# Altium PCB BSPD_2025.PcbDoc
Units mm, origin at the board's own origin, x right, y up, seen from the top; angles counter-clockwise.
Board outline 53 x 50 mm, 2 copper layers (Top Layer, Bottom Layer); 77 components, 28 nets, 170 pads, 103 vias.
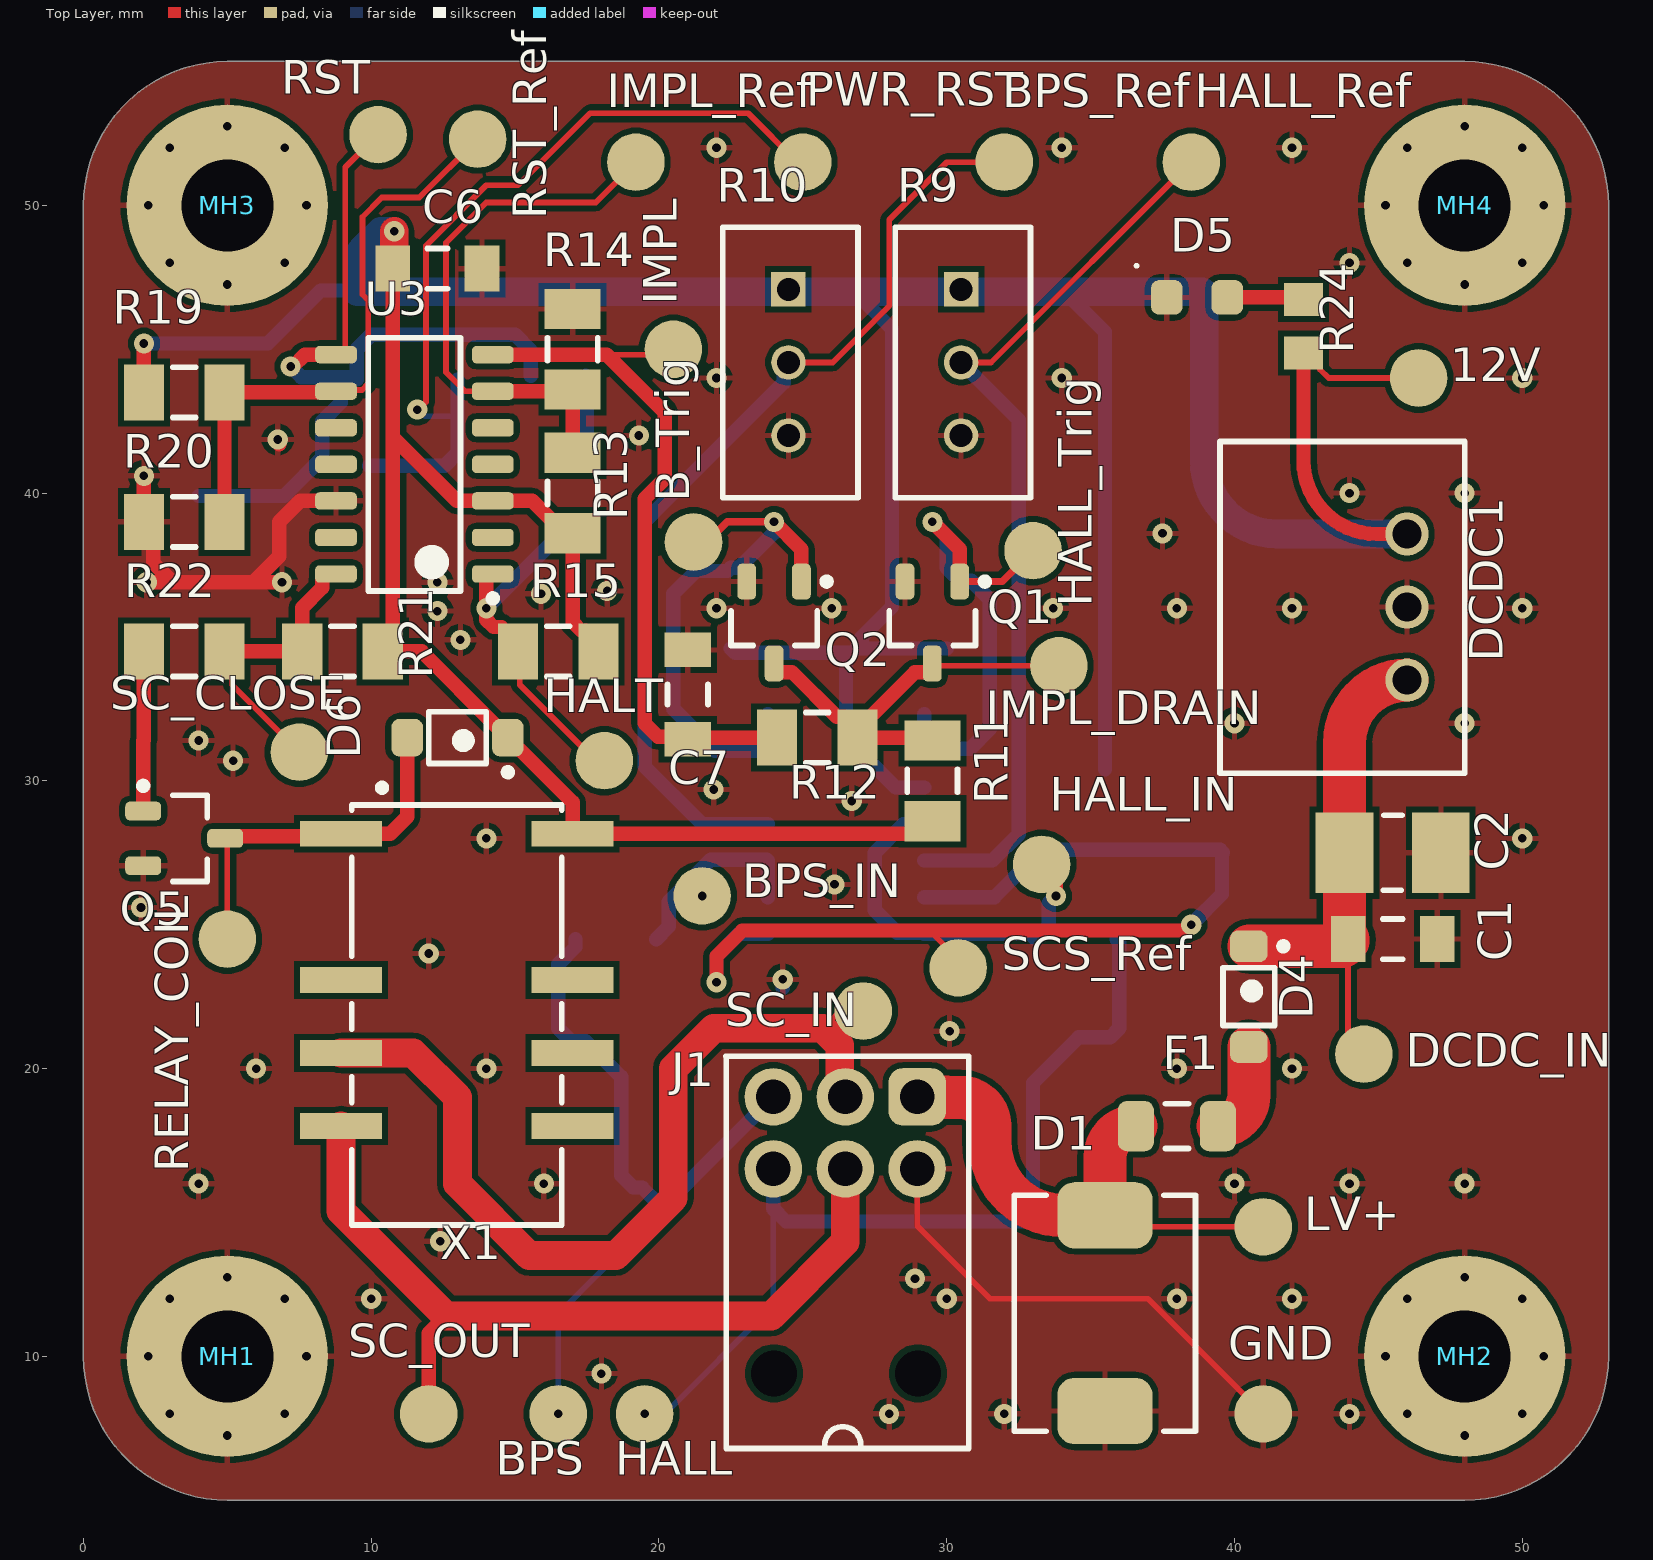
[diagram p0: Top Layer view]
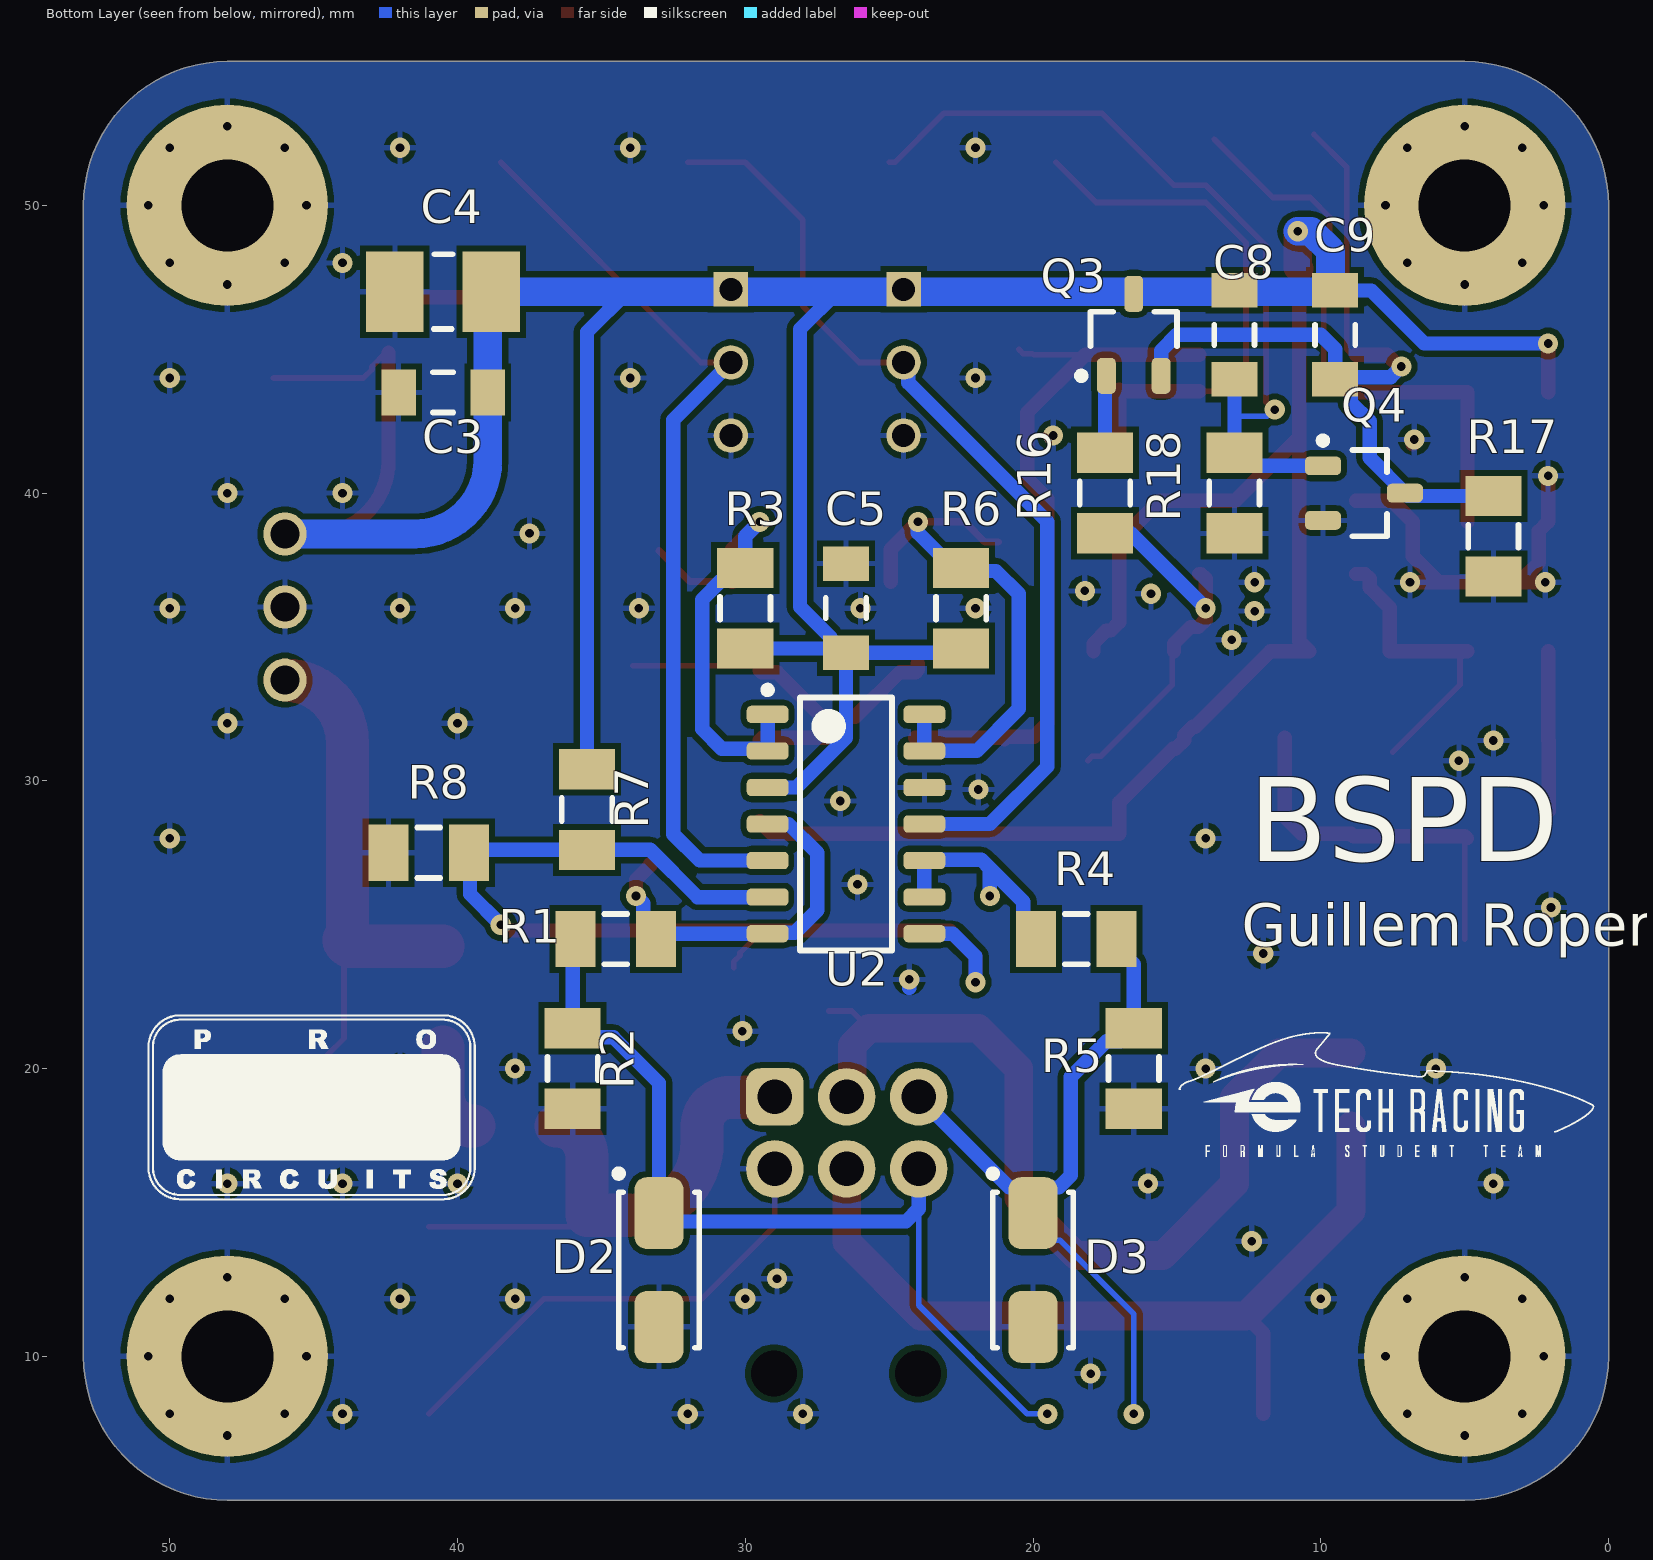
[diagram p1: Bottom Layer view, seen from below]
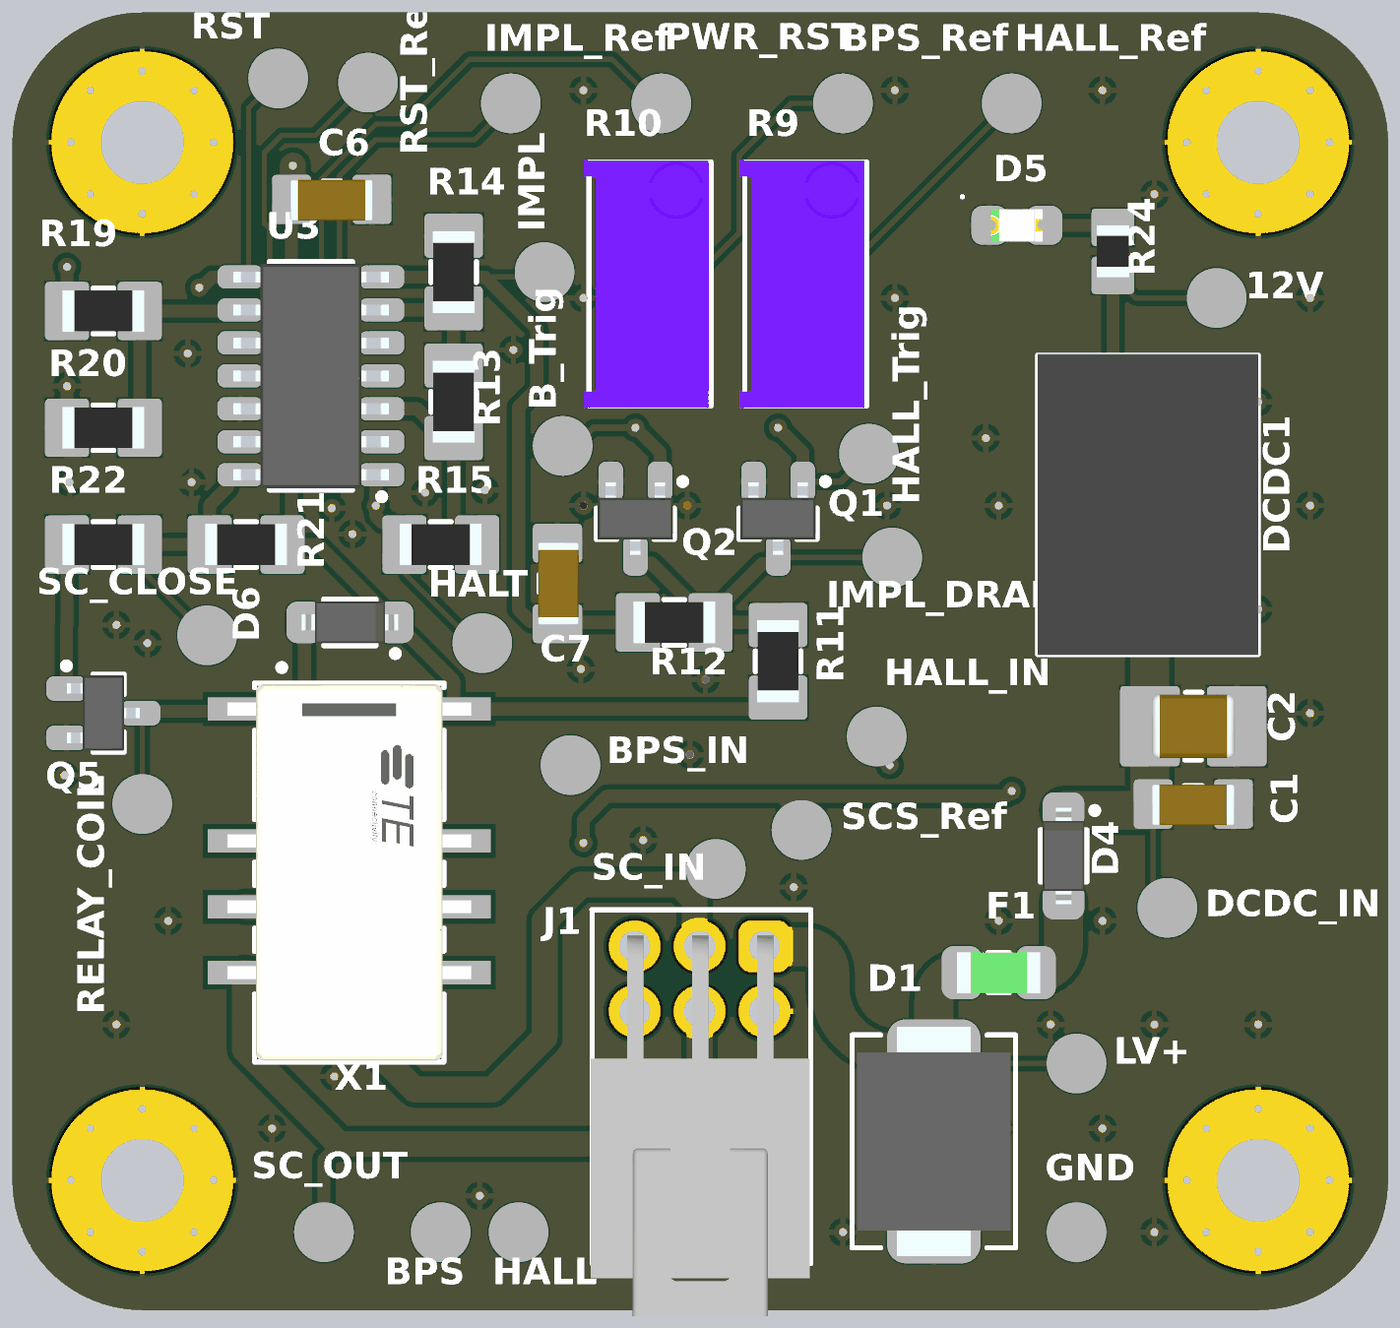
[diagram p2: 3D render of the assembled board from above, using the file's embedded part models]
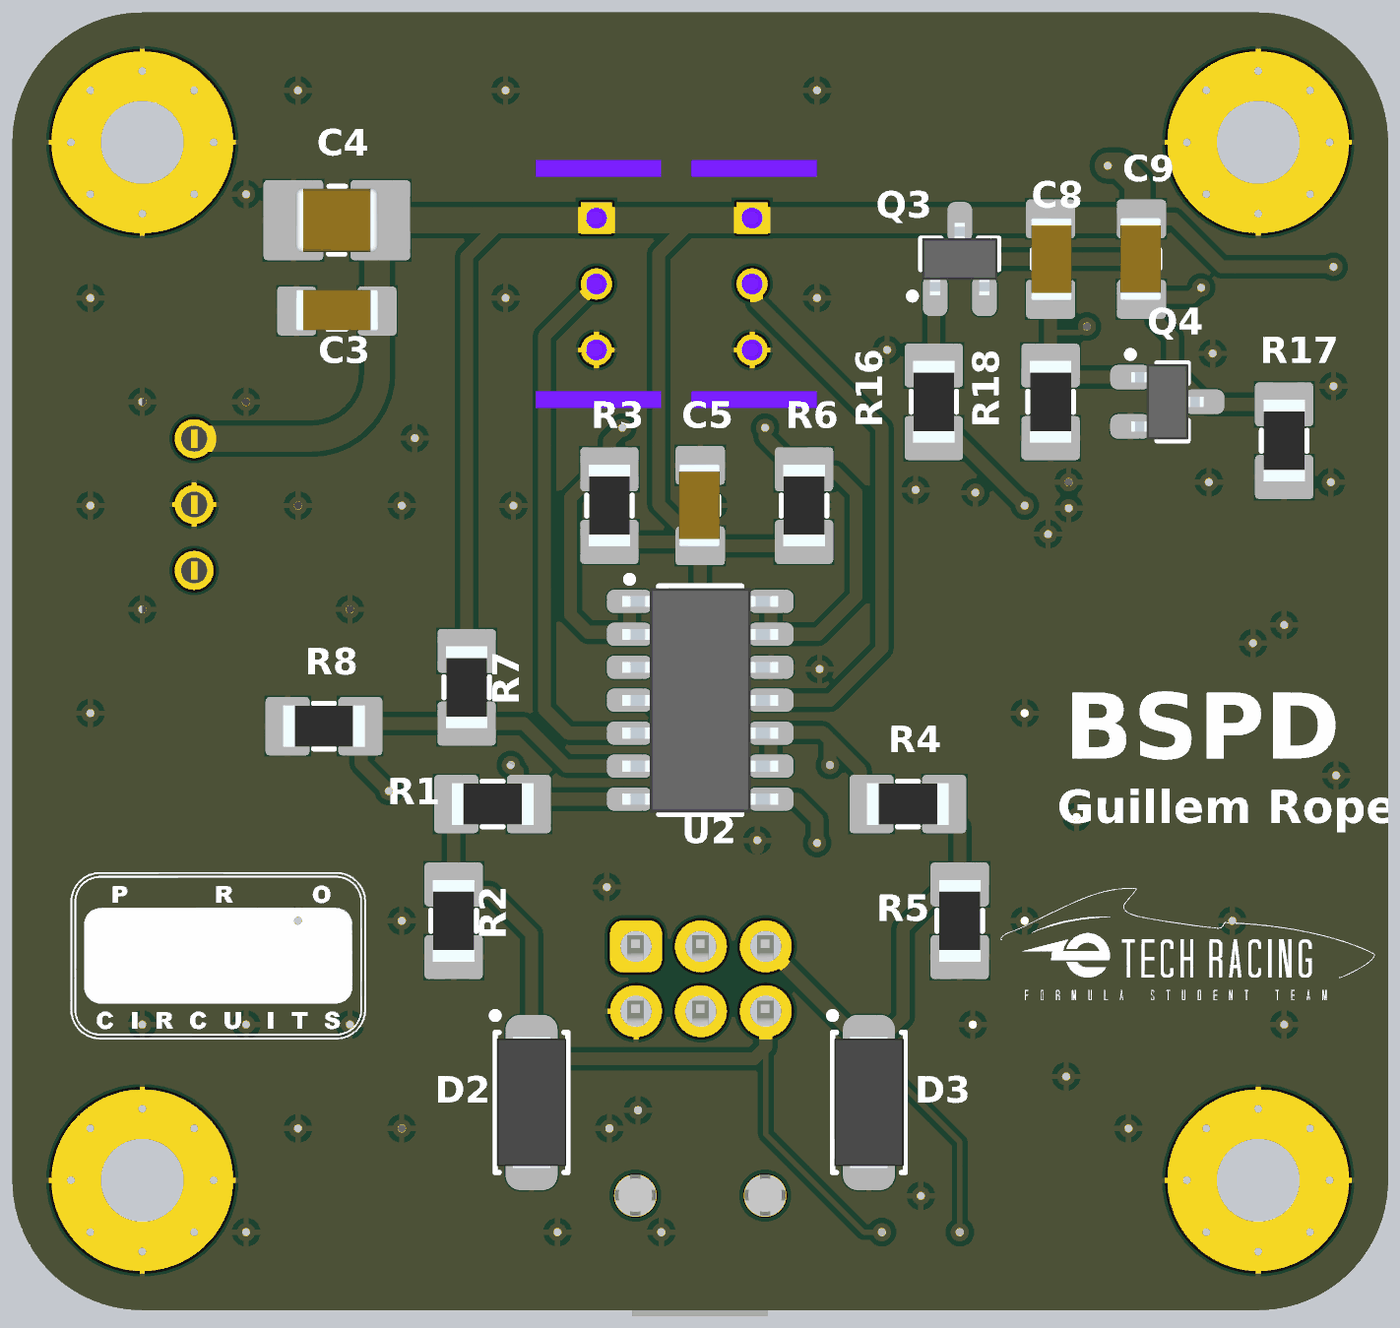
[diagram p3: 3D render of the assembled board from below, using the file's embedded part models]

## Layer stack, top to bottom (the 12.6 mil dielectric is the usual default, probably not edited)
Top Solder: solder mask 0.0102, Solder Resist, Dk 3.5
Top Layer: signal copper 0.0356
Dielectric 1: dielectric 0.32, FR-4, Dk 4.8
Bottom Layer: signal copper 0.0356
Bottom Solder: solder mask 0.0102, Solder Resist, Dk 3.5

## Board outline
0,10 0,50 cw(c5,50) 5,55 48,55 cw(c48,50) 53,50 53,10 cw(c48,10) 48,5 5,5 cw(c5,10)

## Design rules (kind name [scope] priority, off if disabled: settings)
Clearance [All] p1: gap=0.2 ignorepadtopadclearanceinfootprint=FALSE
HoleSize [All] p1: absolutevalues=TRUE maxlimit=5 minlimit=0.2 maxpercent=80.000 minpercent=20.000
HoleToHoleClearance [All] p1: gap=0.3 allowstackedmicrovias=TRUE
MinimumSolderMaskSliver [All] p1: minsoldermaskwidth=0.2
PasteMaskExpansion [All] p1: expansion=0.15
PlaneClearance [All] p1: clearance=0.2
PlaneConnect [All] p1: planeconnectstyle=Relief reliefexpansion=0.3 reliefentries=4 reliefconductorwidth=0.2 reliefairgap=0.2
PolygonConnect [All] p1: connectstyle=Relief reliefconductorwidth=0.2 reliefentries=4 polygonreliefangle="90 Angle" airgapwidth=0.2
RoutingCorners [All] p1: cornerstyle=45-Degree minsetback=2.5 maxsetback=2.5
RoutingVias [All] p1: holewidth=0.3 width=0.5 viastyle="Through Hole" minholewidth=0.3 minwidth=0.5 maxholewidth=2 maxwidth=2.5
SilkToSilkClearance [All] p1: silktosilkclearance=0.2
SilkToSolderMaskClearance [IsPad] p1: minsilkscreentomaskgap=0 clearancetoexposedcopper=TRUE
SolderMaskExpansion [All] p1: expansion=0.1 istentingtop=FALSE
UnRoutedNet [All] p1: checkbadconnections=TRUE
Width [All] p1: maxlimit=5 minlimit=0.2 preferedwidth=0.2
20 further rules are at their usual default settings.

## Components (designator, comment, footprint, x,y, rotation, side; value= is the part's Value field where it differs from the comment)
12V "TestPoint" TestPoint 46.4,44 r90 top
B_Trig "TestPoint" TestPoint 21.2,38.3 r90 top (schematic designator BRAKE_Trig)
BPS "TestPoint" TestPoint 16.5,8 r90 top
BPS_IN "TestPoint" TestPoint 21.5,26 r90 top
BPS_Ref "TestPoint" TestPoint 32,51.5 r90 top
C1 "885012008055" C1206FNPC-RW 45.5,24.5 r180 top
C2 "GRJ32ER71H106KE11L" C10u-50V-1210FNPMLCC-X7R 45.5,27.5 r180 top
C3 "885012008055" C1206FNPC-RW 40.5,43.5 r180 bottom
C4 "GRJ32ER71H106KE11L" C10u-50V-1210FNPMLCC-X7R 40.5,47 r180 bottom
C5 "885012208058" C1206FNPC-RW 26.5,36 r90 bottom
C6 "885012208058" C1206FNPC-RW 12.3,47.8 r180 top
C7 "885012208018" C1206FNPC-RW 21,33 r270 top
C8 "885012208058" C1206FNPC-RW 13,45.5 r270 bottom
C9 "885012208036" C1206FNPC-RW 9.5,45.5 r90 bottom
D1 "824551301" DTVS-DO-214AB 35.5,11.5 r90 top
D2 "824501600" DTVS-DO-214AC 33,13 r90 bottom
D3 "824501600" DTVS-DO-214AC 20,13 r90 bottom
D4 "MBR0530" DSC-SOD123 40.5,22.5 r270 top
D5 "150080VS75000" LED_0805_WE 38.7,46.8 r0 top
D6 "MBR0530" DSC-SOD123 13,31.5 r180 top
DCDC1 "173951236" DCDC_Magi3c 46,36.04 r270 top
DCDC_IN "TestPoint" TestPoint 44.5,20.5 r90 top
F1 "0437001.WRA" Fuse_1206 38,18 r0 top
GND "TestPoint" TestPoint 41,8 r90 top
HALL "TestPoint" TestPoint 19.5,8 r90 top
HALL_IN "TestPoint" TestPoint 33.3,27.1 r90 top
HALL_Ref "TestPoint" TestPoint 38.5,51.5 r90 top
HALL_Trig "TestPoint" TestPoint 33,38 r90 top
HALT "TestPoint" TestPoint 18.1,30.7 r90 top
IMPL "TestPoint" TestPoint 20.5,45 r90 top
IMPL_DRAIN "TestPoint" TestPoint 33.9,34 r90 top
IMPL_Ref "TestPoint" TestPoint 19.2,51.5 r90 top
J1 "J_NanoFit_2x3" J_NanoFit_2x3 26.5,13 r0 top
LV+ "TestPoint" TestPoint 41,14.5 r90 top
MH1 "Mounting_Hole_M3" Mounting_Hole_M3 5,10 r0 top
MH2 "Mounting_Hole_M3" Mounting_Hole_M3 48,10 r0 top
MH3 "Mounting_Hole_M3" Mounting_Hole_M3 5,50 r0 top
MH4 "Mounting_Hole_M3" Mounting_Hole_M3 48,50 r0 top
PWR_RST "TestPoint" TestPoint 25,51.5 r90 top
Q1 "CPH3455-TL-H" TRT-NCH-3/35-CPH 29.5,35.5 r270 top
Q2 "CPH3455-TL-H" TRT-NCH-3/35-CPH 24,35.5 r270 top
Q3 "CPH3455-TL-H" TRT-NCH-3/35-CPH 16.5,45.5 r90 bottom
Q4 "CPH3455-TL-H" TRT-NCH-3/35-CPH 8.5,40 r180 bottom
Q5 "CPH3455-TL-H" TRT-NCH-3/35-CPH 3.5,28 r0 top
R1 "CRCW120610K0FKEA" R1206FTK-W 34.5,24.5 r180 bottom
R2 "CRCW120610K0FKEA" R1206FTK-W 36,20 r90 bottom
R3 "CRCW120610K0FKEA" R1206FTK-W 30,36 r90 bottom
R4 "CRCW120610K0FKEA" R1206FTK-W 18.5,24.5 r0 bottom
R5 "CRCW120610K0FKEA" R1206FTK-W 16.5,20 r90 bottom
R6 "CRCW120610K0FKEA" R1206FTK-W 22.5,36 r90 bottom
R7 "CRCW120610K0FKEA" R1206FTK-W 35.5,29 r270 bottom
R8 "CR1206-FX-2201ELF" R1206FTK-W 41,27.5 r180 bottom
R9 "R10k-VTR" R10k-VTR 30.5,44.54 r0 top value=10k
R10 "R10k-VTR" R10k-VTR 24.5,44.54 r0 top value=10k
R11 "CRCW120610K0FKEA" R1206FTK-W 29.5,30 r90 top
R12 "CRCW120610K0FKEA" R1206FTK-W 25.5,31.5 r180 top
R13 "CRS1206-FX-4701ELF" R1206FTK-W 17,40 r270 top
R14 "CRCW120610K0FKEA" R1206FTK-W 17,45 r270 top
R15 "CRCW120610K0FKEA" R1206FTK-W 16.5,34.5 r180 top
R16 "CRG1206F100R" R1206FTK-W 17.5,40 r90 bottom
R17 "HVC1206-2M0FT3" R1206FTK-W 4,38.5 r90 bottom
R18 "CRCW120610K0FKEA" R1206FTK-W 13,40 r90 bottom
R19 "CRCW120610K0FKEA" R1206FTK-W 3.5,43.5 r180 top
R20 "CRCW120610K0FKEA" R1206FTK-W 3.5,39 r0 top
R21 "CRCW120610K0FKEA" R1206FTK-W 9,34.5 r180 top
R22 "CRG1206F100R" R1206FTK-W 3.5,34.5 r180 top
R24 "CR0805-JW-102ELF" R0805FTK 42.4,45.8 r270 top
RELAY_COIL "TestPoint" TestPoint 5,24.5 r90 top
RST "TestPoint" TestPoint 10.237,52.46 r90 top
RST_Ref "TestPoint" TestPoint 13.7,52.3 r90 top
SC_CLOSE "TestPoint" TestPoint 7.5,31 r90 top
SC_IN "TestPoint" TestPoint 27.1,22 r90 top
SC_OUT "TestPoint" TestPoint 12,8 r90 top
SCS_Ref "TestPoint" TestPoint 30.4,23.5 r90 top
U2 "LM339D" Array_4_Amp_LM339D 26.5,28.5 r180 bottom
U3 "LM339D" Array_4_Amp_LM339D 11.5,41 r180 top
X1 "Relay_SPDT_12V" FP-4-1393789-5-0 12.975,21.86 r270 top

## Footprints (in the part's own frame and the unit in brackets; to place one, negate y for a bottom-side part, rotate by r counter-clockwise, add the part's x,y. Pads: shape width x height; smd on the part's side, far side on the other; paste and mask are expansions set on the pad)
Array_4_Amp_LM339D [mm] "SOIC, 14-Leads, Body 8,65x3,90mm, Pitch 1,27mm, IPC Medium Density"
  rrect50% 1.45x0.6 smd: 1(-2.725,3.81) 2(-2.725,2.54) 3(-2.725,1.27) 4(-2.725,0) 5(-2.725,-1.27) 6(-2.725,-2.54) 7(-2.725,-3.81) 8(2.725,-3.81) 9(2.725,-2.54) 10(2.725,-1.27) 11(2.725,0) 12(2.725,1.27) 13(2.725,2.54) 14(2.725,3.81)
  silkscreen extent -2.85,-4.4 1.6,4.78, body extent -3,-4.33 3,4.33, height 1.75
C10u-50V-1210FNPMLCC-X7R [mm]
  rect 2x2.8 smd: 1(-1.675,0) 2(1.675,0)
  silkscreen extent -0.33,-1.3 0.33,1.3, body extent -1.6,-1.25 1.6,1.25, height 2.78
C1206FNPC-RW [mm] "Chip Capacitor, 2-Leads, Body 3,20x1,60mm, IPC Medium Density"
  rect 1.2x1.6 smd: 1(-1.55,0) 2(1.55,0)
  silkscreen extent -0.35,-0.7 0.35,0.7, body extent -1.59,-0.77 1.61,0.83, height 0.91
DCDC_Magi3c [mm]
  round 1.5 hole 1: 1(2.54,0) 2(0,0) 3(-2.54,0)
  silkscreen extent -5.75,-6.5 5.77,2, body extent -5.8,-6.5 5.8,2, height 10.2
DSC-SOD123 [mm] "SOIC, 2-Leads, Body 1,60x2,69mm, Pitch 1,27mm, IPC Low Density"
  rrect50% 1.1x1.3 smd: A(1.75,0) K(-1.75,0)
  silkscreen extent -1.87,-0.9 1,1.33, body extent -1.86,-0.8 1.86,0.8, height 1.36
DTVS-DO-214AB [mm] "Molded Diode, 2-Leads, Body 7,94x5,90mm"
  rrect50% 2.3x3.3 smd: 1(-3.4,0) 2(3.4,0)
  silkscreen extent -4.1,-3.15 4.1,3.15, body extent -4.42,-2.95 4.42,2.95, height 2.9
DTVS-DO-214AC [mm] "Molded Diode, 2-Leads, Body 5,11x2,67mm, IPC Medium Density"
  rrect50% 2.5x1.7 smd: 1(-1.975,0) 2(1.975,0)
  silkscreen extent -2.7,-1.4 3.47,1.53, body extent -2.56,-1.34 2.56,1.34, height 2.5
FP-4-1393789-5-0 [mm]
  rect 0.9x2.85 smd paste+0 mask+0: 1(-6.3,-4.025) 3(-1.22,-4.025) 4(1.32,-4.025) 5(3.86,-4.025) 8(3.86,4.025) 9(1.32,4.025) 10(-1.22,4.025) 12(-6.3,4.025)
  silkscreen extent -8.02,-3.65 7.3,3.65, body extent -7.4,-5.55 7.4,5.55, height 0.25
Fuse_1206 [mm] "Chip Resistor, 2-Leads, Body 3,20x1,58mm, IPC Medium Density"
  rrect50% 1.25x1.75 smd: 1(-1.425,0) 2(1.425,0)
  silkscreen extent -0.4,-0.77 0.4,0.77, body extent -1.6,-0.79 1.6,0.79, height 0.86
J_NanoFit_2x3 [mm]
  rrect50% 2x2 hole 1.2: 1(2.475,6.015)
  round 2 hole 1.2: 2(-0.025,6.015) 3(-2.525,6.015) 4(2.475,3.515) 5(-0.025,3.515) 6(-2.525,3.515)
  round 1.524 hole 1.6: 7(-2.5,-3.59) 7(2.5,-3.59)
  silkscreen extent -4.18,-6.2 4.26,7.42, body extent -4.22,-8.23 4.22,6.43, height 9.35
LED_0805_WE [mm] "SODFL, 2-Leads, Body 1,60x3,20mm, IPC Medium Density"
  rrect50% 1.1x1.2 smd: A(1.05,0) K(-1.05,0)
  silkscreen extent -2.15,1.05 -2.05,1.15, body extent -1,-0.62 1,0.63, height 0.7
Mounting_Hole_M3 [mm]
  round 7 hole 3.2: 1(0,0)
R10k-VTR [mm]
  rect 1.2x1.2 hole 0.8: 1(0,2.54)
  round 1.2 hole 0.8: 2(0,-2.54) 3(0,0)
  silkscreen extent -2.29,-4.7 2.41,4.7, body extent -2.49,-4.78 2.34,4.78, height 11.09
R0805FTK [mm] "Chip Resistor, 2-Leads, Body 2,00x1,25mm, IPC Medium Density"
  rect 1.15x1.35 smd: 1(-0.925,0) 2(0.925,0)
  body extent -1,-0.63 1,0.63, height 0.65
R1206FTK-W [mm] "Chip Resistor, 2-Leads, Body 3,15x1,60mm, IPC Medium Density"
  rect 1.4x1.95 smd: 1(-1.4,0) 2(1.4,0)
  silkscreen extent -0.4,-0.87 0.4,0.87, body extent -1.58,-0.8 1.58,0.8, height 0.61
TestPoint [mm]
  round 2 smd: 1(0,0)
TRT-NCH-3/35-CPH [mm] "SOT23, 3-Leads, Body 2,90x2,80mm, Pitch 0,95mm, IPC Low Density"
  rrect50% 1.25x0.65 smd: D(1.425,0) G(-1.425,0.95) S(-1.425,-0.95)
  silkscreen extent -1.55,-1.5 0.8,1.95, body extent -1.4,-1.45 1.4,1.45, height 1.06

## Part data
12V B_Trig BPS BPS_IN BPS_Ref DCDC_IN GND HALL HALL_IN HALL_Ref HALL_Trig HALT IMPL IMPL_DRAIN IMPL_Ref LV+ PWR_RST RELAY_COIL RST RST_Ref SC_CLOSE SC_IN SC_OUT SCS_Ref: "Test Point 1x1 mm"
C1 C3: library part C10n-50V-1206FNPC-C0G/NP0, "Cap Cer 10000PF 50V C0G/NP0 1206", Capacitance=10nF, Case Code (Imperial)=1206, Case Code (Metric)=3216, Manufacturer="Wurth Electronics", Max Operating Temperature=125°C, Min Operating Temperature=-55°C, Supplier Part Number 1=710-885012008055, Tolerance=5%, Voltage Rating=50V
C2 C4: library part C10u-50V-1210FNPMLCC-X7R, "Multilayer Ceramic Capacitors MLCC - SMD/SMT 1210 10uF 50volts X7R +/-10% Soft Term", Capacitance=10uF, Case Code (Imperial)=1210, Case Code (Metric)=3225, Manufacturer=Murata, Max Operating Temperature=125°C, Min Operating Temperature=-55°C, Tolerance=10%, Voltage Rating=50V
C5 C6 C8: library part C100n-25V-1206FNPC-X7R, "Cap Cer 0.1UF 25V X7R 1206", Capacitance=100nF, Case Code (Imperial)=1206, Case Code (Metric)=3216, Manufacturer="Wurth Electronics", Max Operating Temperature=125°C, Min Operating Temperature=-55°C, Supplier Part Number 1=732-8109-1-ND, Tolerance=10%, Voltage Rating=25V
C7: library part C10u-10V-1206FNPC-X7R, "Cap, 10ΜF, 10V, 10%, X7R, 1206", Capacitance=10uF, Case Code (Imperial)=1206, Case Code (Metric)=3216, Manufacturer 1="Wurth Electronics", Max Operating Temperature=125°C, Min Operating Temperature=-55°C, Supplier Part Number 1=732-7565-1-ND, Tolerance=10%, Voltage Rating=10V
C9: library part C1u-16V-1206FNPC-X7R, "Cap Cer 1UF 16V X7R 1206", Capacitance=1uF, Case Code (Imperial)=1206, Case Code (Metric)=3216, Manufacturer="Wurth Electronics", Max Operating Temperature=125°C, Min Operating Temperature=-55°C, Supplier Part Number 1=710-885012208036, Tolerance=10%, Voltage Rating=16V
D1: library part DTVS-40V-DO-214AB, "TVS diode [Würth Elektronik] 824551301 TVS diode", Clamping Voltage=48.4V, Manufacturer="Wurth Electronics", Max Breakdown Voltage=35.05V, Max Operating Temperature=150°C, Min Operating Temperature=-65°C, Peak Pulse Current=62A, Peak Pulse Power=3kW, Power Line Protection=No, Resistor Type=Zener, Reverse Standoff Voltage=30V, Supplier Part Number 1=9217092P
D2 D3: library part DTVS-6V-DO-214AC, "TVS diode [Würth Elektronik] 824501600 TVS diode", Clamping Voltage=10.3V, Manufacturer="Wurth Electronics", Max Breakdown Voltage=7.02V, Max Operating Temperature=150°C, Min Operating Temperature=-65°C, Peak Pulse Current=38.8A, Peak Pulse Power=400W, Power Line Protection=No, Resistor Type=Zener, Reverse Standoff Voltage=6V, Supplier Part Number 1=710-824501600
D4 D6: library part DSC-0.5/30-SOD123, "VR=30V IF=500mA 30pF P=410mW", Average Rectified Current=500mA, Forward Voltage=430mV, Max Forward Surge Current (Ifsm)=5.5A, Max Repetitive Reverse Voltage (Vrrm)=30V, Max Reverse Current=130uA, Package Quantity=1, Supplier Part Number 1=15R3453
D5: library part LEDVS-0805-40, "Led, Green, 570 Nm, 2 V, 30 Ma, 40 Mcd Rohs Compliant: Yes", Case Code (Imperial)=0805, Case Code (Metric)=2012, Color=Green, Forward Current=30mA, Forward Voltage=2V, Manufacturer 1="Wurth Electronics", Max Operating Temperature=85°C, Min Operating Temperature=-40°C, Package Quantity=4000, Supplier Part Number 1=8154237, Test Current=20mA
DCDC1: library part DCDC-36V/12V-0.5A, "Fdsm Fixed Step Down Regulator M", Manufacturer 1="Wurth Electronics", Supplier Part Number 1=732-173951236-ND
F1: library part Fuse_1A_63V_1206, "Fuse Chip Fast Acting 1A 63V SMD Solder Pad 1206 Ceramic T/R Automotive", Case Code (Imperial)=1206, Case Code (Metric)=3216, Current Rating=1A, Manufacturer=Littelfuse, Max Operating Temperature=150°C, Min Operating Temperature=-55°C, Supplier Part Number 1=F10001CT-ND, Voltage Rating (AC)=63V
Q1 Q2 Q3 Q4 Q5: library part TRT-NCH-3/35-CPH, "CPH3455-TL-H N-channel MOSFET Transistor; 3 A; 35 V; 3-Pin CPH", Case/Package=SC, Continuous Drain Current (ID)=3A, Drain to Source Breakdown Voltage=35V, Drain to Source Resistance=108mR, Gate to Source Voltage (Vgs)=20V, Input Capacitance=186pF, Manufacturer="ON Semiconductor", Max Operating Temperature=150°C, Max Power Dissipation=1W, Min Operating Temperature=-55°C, Package Quantity=3000, Supplier Part Number 1=8009989
R1 R3 R4 R6 R11 R14 R15 R19 R20 R21: library part R10k-1206FTK, "Res Thick Film 1206 10K Ohm 1% 0.25W(1/4W) +/-100ppm/ßC Pad SMD Automotive T/R", Case Code (Imperial)=1206, Case Code (Metric)=3216, Package Quantity=10, Package Shape=Rectangular, Resistance=10kR, Resistance Tolerance=1%, Resistor Type="Thick Film", Supplier Part Number 1=70201262, Temperature Coefficient=100ppm/°C, Voltage Rating=200V
R2 R5 R7 R12 R18: library part R51k-1206FTK, "Res Thick Film 1206 51K Ohm 1% 1/4W ±100ppm/°C Molded SMD SMD Punched Carrier T/R", Case Code (Imperial)=1206, Case Code (Metric)=3216, Current Rating=2A, Manufacturer=Panasonic, Manufacturer Part Number=ERJ-S08F5102V, Max Operating Temperature=155°C, Max Power Dissipation=250mW, Min Operating Temperature=-55°C, Package Quantity=5000, Resistance=51kR, Resistor Type="Thick Film", Supplier Part Number 1=667-ERJ-S08F5102V, Temperature Coefficient=100ppm/°C, Tolerance=1%, Voltage Rating=150V, Voltage Rating (DC)=200V
R8: library part R2.2K-1206FTK, "Res Thick Film 1206 2.2K Ohm 1% 1/4W ±100ppm/°C Molded SMD SMD Paper Tape on Plastic Reel", Case Code (Imperial)=1206, Case Code (Metric)=3216, Manufacturer 1=Bourns, Max Operating Temperature=155°C, Max Power Dissipation=250mW, Min Operating Temperature=-55°C, Package Quantity=5000, Resistance=2.2kR, Resistance Tolerance=1%, Resistor Type="Thick Film", Supplier Part Number 1=CR1206-FX-2201ELFCT-ND, Temperature Coefficient=100ppm/°C, Voltage Rating=200V
R9 R10: library part CMP-00072-1, "Trimmer, Cermet, Rest 10 Kilohms, PCB, 25 Turns, Pwr-Rtg 0.5W, 3296 Series", Color=Blue, Insulation Resistance=1GR, Manufacturer=Bourns, Manufacturer Part Number=3296W-1-103LF, Max Operating Temperature=125°C, Max Power Dissipation=500mW, Min Operating Temperature=-55°C, Package Quantity=50, Resistance Tolerance=10%, Resistor Type=Cermet, Temperature Coefficient=100ppm/°C
R13: library part R4.7K-1206FTK, "Res Thick Film 1206 4.7K Ohm 1% 1/2W ±100ppm/°C Molded SMD T/R", Case Code (Imperial)=1206, Case Code (Metric)=3016, Manufacturer 1="Bourns JW Miller", Max Operating Temperature=155°C, Max Power Dissipation=500mW, Min Operating Temperature=-55°C, Resistance=4.7kR, Resistor Type="Thick Film", Supplier Part Number 1=CRS1206-FX-4701ELFCT-ND, Temperature Coefficient=100ppm/°C, Tolerance=1%, Voltage Rating=400V
R16 R22: library part R100-1206FTK, "Res Thick Film 1206 100 Ohm 1% 0.25W(1/4W) ±200ppm/C Pad SMD T/R", Case Code (Imperial)=1206, Case Code (Metric)=3216, Manufacturer="TE Connectivity", Max Operating Temperature=125°C, Max Power Dissipation=250mW, Min Operating Temperature=-55°C, Number of Resistors=1, Package Quantity=5000, Resistance=100R, Resistor Type="Thick Film", Supplier Part Number 1=A106068CT-ND, Temperature Coefficient=200ppm/°C, Tolerance=1%, Voltage Rating=200V
R17: library part R2M-1206FTK, "Res Thick Film 1206 2M Ohm 1% 0.3W ±100ppm/C Pad SMD T/R", Case Code (Imperial)=1206, Case Code (Metric)=3216, Manufacturer="TT Welwyn", Power rating=300mW, Resistance=2MR, Resistor Type="Thick Film", Supplier Part Number 1=6119491, Temperature Coefficient=100ppm/°C, Tolerance=1%, Voltage Rating=1kV
R24: library part R1k-0805FTK, "Res Thick Film 0805 1K Ohm 5% 1/8W ±200ppm/°C Molded SMD SMD Paper Tape on Plastic Reel", Case Code (Imperial)=0805, Case Code (Metric)=2012, Manufacturer 1=Bourns, Max Operating Temperature=155°C, Max Power Dissipation=125mW, Min Operating Temperature=-55°C, Package Quantity=1, Resistance=1kR, Resistor Type="Thick Film", Temperature Coefficient=200ppm/°C, Tolerance=5%, Voltage Rating=150V
U2 U3: library part Array_4_Comp_LM339D, "Comparator Quad ±18V/36V 14-Pin SOIC Tube", Case/Package=SOIC, Dual Supply Voltage=9V, Input Bias Current=250nA, Input Offset Voltage (Vos)=5mV, Manufacturer="Texas Instruments", Max Dual Supply Voltage=15V, Max Operating Temperature=70°C, Max Supply Current=500uA, Max Supply Voltage=30V, Min Dual Supply Voltage=1V, Min Operating Temperature=0°C, Min Supply Voltage=2V, Nominal Supply Current=2mA, Output Current=20mA, Output Current per Channel=6mA, Package Quantity=50, Quiescent Current=2.5mA, Supplier Part Number 1=296-1013-5-ND, Voltage Gain=106.02dB
X1: library part CMP-00219-1, "RF Relay, 2 Form C, DPDT, Momentary, 0.012A (Coil), 12VDC (Coil), 140mW (Coil), 5A (Contact), 220VDC (Contact), 900MHz, 60W (RF Input), DC Input, Random, AC/DC Output, Surface Mount-Straight", Coil Current(DC)-Max=12mA, Coil Operate Voltage(DC)=26.15V, Coil Power=140mW, Coil Release Voltage(DC)=1.2V, Coil Resistance=1.029kR, Coil Voltage(DC)-Max=12V, Contact AC Max Power Rating R Load=62.5VA@250VAC, Contact AC Max Rating R Load=5A@250VAC, Contact Current(AC)-Max=5A, Contact DC Max Power Rating R Load=60W@220VDC, Contact DC Max Rating R Load=5A@220VDC, Contact Resistance=50mR, Contact Voltage(AC)-Max=250V, Contact Voltage(DC)-Max=220V, Dielectric Strength Between Coil and Contacts=1500Vrms, Dielectric Strength Between Open Contacts=1000Vrms, Input Power-Max=60W, Insulation Resistance=1GR, Manufacturer Series=1393789, Max Operating Temperature=85°C, Min Operating Temperature=-40°C, Operating Frequency-Max=900MHz, Operating Frequency-Min=100MHz

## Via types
v1: diameter 0.7, hole 0.3, Top Layer to Bottom Layer, tented both sides, 103 vias

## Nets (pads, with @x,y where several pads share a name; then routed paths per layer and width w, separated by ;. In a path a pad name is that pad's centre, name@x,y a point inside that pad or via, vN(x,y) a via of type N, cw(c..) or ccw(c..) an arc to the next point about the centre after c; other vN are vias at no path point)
+12: 12V.1 C3.2 C4.2 C5.1 C6.2 C8.1 C9.2 D6.K DCDC1.3 Q3.D R3.1 R6.1 R7.1 R9.1 R10.1 R11.1 R13.2 R15.1 R19.2 R21.1 R24.2 U2.3 U3.3 X1.12 | length 164.1
  Top Layer w0.2: R24.2 42.5,44.875 42.975,44.4 42.975,44.3 43.275,44 12V.1
  Top Layer w0.5: R19.2 v1(2.1,45.2) ; C6.2 10.75,41.95 ; R15.1 17.9,34.775 17.45,35.225 17.293,35.225 17,35.518 R13.2 16.725,38.6 15.595,39.73 12.97,39.73 10.75,41.95 ; R11.1 29.06,28.16 X1.12 17,29.25 15.135,31.115 15.048,31.115 14.75,31.414 D6.K 14.75,31.586 14.452,31.885 14.365,31.885 11.75,34.5 R21.1 10.75,34.85 10.75,41.95 ; R24.2 42.4,41.12 ccw(c44.94,41.12) 44.94,38.58 DCDC1.3
  Top Layer w1: C6.2 10.8,47.85 v1(10.8,49.1)
  Bottom Layer w0.5: v1(2.1,45.2) 6.4,45.2 8.243,47.043 9.493,47.043 C9.2 ; R6.1 22.65,34.45 C5.1 ; 26.8,47 28.1,45.7 28.1,36.05 27.05,35 27.05,34.8 C5.1@26.85,34.6 ; U2.3 28.23,29.77 26.5,31.5 C5.1 ; R3.1 C5.1@26.85,34.6 ; 34.1,47 35.5,45.6 R7.1 ; C5.1 26.7,34.45 C5.1@26.85,34.6
  Bottom Layer w1: v1(10.8,49.1) 10.343,49.1 9.657,48.414 9.657,47.15 9.557,47.05 C9.2 ccw(c9.55,47.05) 9.55,47 26.8,47 34.1,47 C4.2 cw(c38.825,46.875) 38.95,46.875 C3.2 38.95,41.12 ccw(c41.49,41.12) 41.49,38.58 DCDC1.3
Brake_in: BPS.1 D3.2 J1.3 R4.1 R5.2 | length 25.8
  Bottom Layer w0.2: v1(16.5,8) 16.5,11.475 19.062,14.037 19.275,14.037 20,14.763 D3.2
  Bottom Layer w0.5: R4.1 17.1,24.225 16.5,23.625 R5.2 16.95,20.95 17.448,20.95 18.683,19.716 18.683,16.292 19.108,15.867 19.413,15.867 D3.2@20,15.28 ; D3.2 D3.2@20,15.28 ; J1.3 20.827,15.867 20.587,15.867 D3.2@20,15.28
Brake_trig_lvl: BPS_Ref.1 R10.3 U2.11 | length 33.4
  Top Layer w0.2: R10.3 26.04,44.54 28,46.5 28,49.5 30,51.5 BPS_Ref.1
  Bottom Layer w0.5: U2.11 21.5,28.5 19.5,30.5 19.5,39 24.33,43.83 24.33,44.37 R10.3
Brake_trigger: B_Trig.1 Q2.G R6.2 U2.13 U2.14 | length 19.5
  Top Layer w0.254: B_Trig.1 21.672,38.3 22.372,39 v1(24,39)
  Top Layer w0.5: v1(24,39) 24.95,38.05 Q2.G
  Bottom Layer w0.5: U2.14 U2.13 21.96,31.04 20.5,32.5 20.5,36.5 21.293,37.293 22.393,37.293 R6.2 22.775,37.4 24,38.625 v1(24,39)
GND: C1.1 C2.1 C3.1 C4.1 C5.2 C6.1 C7.1 D1.1 D2.1 D3.1 D5.K DCDC1.2 GND.1 J1.4 MH1.1 MH2.1 MH3.1 MH4.1 Q1.S Q2.S Q4.S Q5.S R2.1 R5.1 R8.1 R9.2 R10.2 R14.1 R17.1 R18.1 R20.1 U2.12 U3.12 | length 31.2
  Top Layer w0.2: J1.4 28.975,14.525 31.5,12 37,12 GND.1
  Top Layer w0.5: v1(2.1,40.6) R20.1 2.418,38.682 2.418,37.582 3.1,36.9 ; v1(2.2,36.9) 3.1,36.9 ; v1(6.751,41.863) 6.751,41.749 v1@6.8,41.7 ; v1(6.9,36.9) 5.9,36.9 ; U3.12 7.53,39.73 6.8,39 6.8,37.8 5.9,36.9 ; v1(12.4,14) v1@12.5,14 ; v1@33.6,36 v1(33.7,36) ; 3.1,36.9 5.9,36.9
  Bottom Layer w0.5: v1@17.9,9.4 v1(18,9.4) ; v1@24.3,22.8 v1(24.3,23.1) ; v1@34,43.9 v1(34,44)
  other v1: 5,7.25 48,7.25 3,8 7,8 28,8 32,8 44,8 46,8 50,8 2.25,10 7.75,10 45.25,10 50.75,10 3,12 7,12 10,12 30,12 38,12 42,12 46,12 50,12 28.9,12.7 5,12.75 48,12.75 4,16 16,16 40,16 44,16 48,16 6,20 14,20 38,20 42,20 30.1,21.3 12,24 2,25.6 26.1,26.4 14,28 50,28 26.7,29.3 21.9,29.7 5.2,30.7 4,31.4 40,32 48,32 13.1,34.9 12.3,35.9 22,36 26,36 38,36 42,36 50,36 15.9,36.5 18.2,36.6 12.3,36.9 37.5,38.6 44,40 48,40 19.3,42 22,44 50,44 5,47.25 48,47.25 3,48 7,48 44,48 46,48 50,48 2.25,50 7.75,50 45.25,50 50.75,50 3,52 7,52 22,52 34,52 42,52 46,52 50,52 5,52.75 48,52.75
Hall_in: D2.2 HALL.1 J1.6 R1.1 R2.2 | length 31.6
  Bottom Layer w0.2: v1(19.5,8) 20.2,8 23.975,11.775 23.975,15.125
  Bottom Layer w0.5: J1.6 23.975,15.125 24.413,14.687 32.712,14.687 D2.2 33,19.5 34.582,21.082 35.682,21.082 R2.2 36,24.4 R1.1
Hall_trig_lvl: HALL_Ref.1 R9.3 U2.5 | length 31.8
  Top Layer w0.2: R9.3 31.54,44.54 HALL_Ref.1
  Bottom Layer w0.5: U2.5 31.581,27.23 32.5,28.149 32.5,42.54 R9.3
Hall_trigger: HALL_Trig.1 Q1.G R3.2 U2.1 U2.2 | length 17.6
  Top Layer w0.254: Q1.G 31.925,36.925 HALL_Trig.1
  Top Layer w0.5: v1(29.5,39) 30.45,38.05 Q1.G
  Bottom Layer w0.5: U2.1 U2.2 29.301,31.116 30.816,31.116 31.5,31.8 31.5,36.3 30.85,36.95 30.45,36.95 R3.2 30,38.5 v1(29.5,39)
Halt: HALT.1 R15.2 R16.1 U3.1 | length 13.2
  Top Layer w0.2: R15.2 15.158,34.442 15.158,33.342 17.647,30.853 17.947,30.853 HALT.1
  Top Layer w0.5: U3.1 14.171,37.19 14,37.019 v1(14,36) 14,35.6 14.252,35.348 14.527,35.348 15.1,34.775 R15.2
  Bottom Layer w0.5: v1(14,36) 16.6,38.6 R16.1
Implausability: C7.2 IMPL.1 R12.2 U3.7 | length 25.1
  Top Layer w0.2: 18.19,44.81 19.983,44.81 20.02,44.847 20.347,44.847 IMPL.1
  Top Layer w0.5: U3.7 18.19,44.81 20.201,42.799 20.201,40.501 19.5,39.8 19.5,32 19.968,31.532 20.918,31.532 C7.2 cw(c21.05,31.45) 21.05,31.5 R12.2
LV+_in: D1.2 F1.1 J1.1 LV+.1 | length 18.5
  Top Layer w0.2: D1.2 35.9,14.5 LV+.1
  Top Layer w1.5: J1.1 29.985,19.015 30,19 30.5,19 cw(c30.5,18) 31.5,18 31.5,17.44 ccw(c34.04,17.44) 34.04,14.9 D1.2 35.5,16.925 cw(c36.575,16.925) F1.1
NetBPS_IN_1: BPS_IN.1 R4.2 U2.9 U2.10 | length 7.8
  Bottom Layer w0.5: R4.2 20.337,24.937 20.337,25.798 21.5,26.961 ; v1(21.5,26) 21.5,26.961 ; U2.9 U2.10 23.751,27.254 21.793,27.254 21.5,26.961
NetC1_2: C1.2 C2.2 D4.K DCDC1.1 DCDC_IN.1 | length 18.1
  Top Layer w0.2: C1.2 43.95,21.05 DCDC_IN.1
  Top Layer w1.5: D4.K 43.7,24.25 ccw(c43.7,24.5) C1.2 cw(c43.95,24.625) 43.825,24.625 C2.2 43.825,31.325 cw(c46,31.325) DCDC1.1
NetC8_2: C8.2 PWR_RST.1 Q4.G R18.2 | length 28.9
  Top Layer w0.2: v1(11.6,42.9) 11.633,42.9 11.9,43.167 11.9,48.6 14,50.7 15.1,50.7 17.6,53.2 23.1,53.2 24.8,51.5 PWR_RST.1
  Bottom Layer w0.2: v1(11.6,42.9) 11.642,42.9 11.867,42.675 13,42.675
  Bottom Layer w0.5: Q4.G 12.55,40.95 R18.2 13,42.675 C8.2
NetD4_A: D4.A F1.2 | length 3.4
  Top Layer w1.5: F1.2 ccw(c39.425,19.075) 40.5,19.075 D4.A
NetD5_A: D5.A R24.1 | length 2.7
  Top Layer w0.5: D5.A 42.325,46.8 cw(c42.325,46.725) R24.1
NetD6_A: D6.A Q5.D RELAY_COIL.1 X1.1 | length 12.9
  Top Layer w0.2: Q5.D 5,27.925 RELAY_COIL.1
  Top Layer w0.5: Q5.D 5,28.075 8.865,28.075 X1.1 10.66,28.16 11.25,28.75 D6.A
NetHALL_IN_1: HALL_IN.1 R1.2 U2.4 U2.7 | length 13.3
  Top Layer w0.5: HALL_IN.1 33.3,27.057 33.8,26.557 v1(33.8,26)
  Bottom Layer w0.5: U2.4 28.5,28.5 27.5,27.5 27.5,25.5 28.284,24.716 29.199,24.716 U2.7 32.91,24.69 R1.2 33.55,24.95 33.55,25.75 v1(33.8,26)
NetIMPL_DRAIN_1: IMPL_DRAIN.1 Q1.D Q2.D R11.2 R12.1 | length 15
  Top Layer w0.2: Q1.D 29.575,34 IMPL_DRAIN.1
  Top Layer w0.5: Q2.D 24,33.855 24.075,33.78 24.62,33.78 26.175,32.225 26.45,32.225 R12.1@26.9,31.775 ; R11.2 29.4,31.5 R12.1 R12.1@26.9,31.775 ; Q1.D 29.5,33.842 29.425,33.767 28.892,33.767 R12.1@26.9,31.775
NetIMPL_Ref_1: IMPL_Ref.1 R13.1 R14.2 U3.6 | length 19.2
  Top Layer w0.2: U3.6 13.26,43.54 12.6,44.2 12.6,48.7 14,50.1 17.8,50.1 IMPL_Ref.1
  Top Layer w0.5: U3.6 16.94,43.54 R14.2 R13.1
NetQ3_G: Q3.G R16.2 | length 2.7
  Bottom Layer w0.5: Q3.G 17.5,44.025 R16.2
NetQ5_G: Q5.G R22.2 | length 5.6
  Top Layer w0.5: Q5.G 2.075,31.387 2.1,31.412 R22.2
NetR19_1: R19.1 R20.2 RST_Ref.1 U3.9 | length 20.6
  Top Layer w0.2: U3.9 8.818,43.583 9.683,43.583 9.9,43.8 9.9,46.7 9.7,46.9 9.7,49.6 10.369,50.269 11.669,50.269 RST_Ref.1
  Top Layer w0.5: R20.2 R19.1 8.735,43.5 U3.9
Reset: C9.1 Q3.S Q4.D R17.2 RST.1 U3.8 | length 29.1
  Top Layer w0.2: U3.8 8.904,44.81 9.1,45.006 9.1,51.323 RST.1
  Top Layer w0.5: v1(7.2,44.4) 7.28,44.4 7.69,44.81 U3.8
  Bottom Layer w0.5: R17.2 6.975,39.9 Q4.D 8.3,41.225 8.3,42.5 8.95,43.15 8.95,43.6 9.3,43.95 C9.1@9.487,43.95 ; v1(7.2,44.4) 7.568,44.032 9.418,44.032 C9.1 9.5,45 10,45.5 15,45.5 15.55,44.95 Q3.S
SC_close: R21.2 R22.1 SC_CLOSE.1 U3.14 | length 10.6
  Top Layer w0.2: R22.1 5.158,34.242 5.158,33.342 SC_CLOSE.1
  Top Layer w0.5: R22.1 R21.2 7.6,36.015 8.291,36.706 8.291,37.019 8.462,37.19 U3.14
SC_in: J1.2 SC_IN.1 X1.4 | length 31.7
  Top Layer w0.2: 25.698,21.4 26.298,22 SC_IN.1
  Top Layer w1: X1.4 11.46,20.54 13,19 13,16 15.5,13.5 18.5,13.5 20.5,15.5 20.5,20 21.9,21.4 25.698,21.4 26.284,20.814 26.284,19.206 J1.2
SC_out: J1.5 SC_OUT.1 X1.5 | length 29.2
  Top Layer w0.5: SC_OUT.1 12,10.8 12.6,11.4
  Top Layer w1: X1.5 8.95,15.05 12.6,11.4 23.9,11.4 26.475,13.975 J1.5
SCS_ref_lvl: R7.2 R8.2 SCS_Ref.1 U2.6 U2.8 | length 36.6
  Top Layer w0.2: 29.4,24.8 30.184,24.016 30.184,23.932 30.4,23.716 SCS_Ref.1
  Top Layer w0.5: v1(22,23) 22,23.9 22.9,24.8 29.4,24.8 38.3,24.8 v1(38.5,25)
  Bottom Layer w0.5: v1(22,23) 22,23.9 22.784,24.684 23.769,24.684 U2.8 ; U2.6 31.66,25.96 33.3,27.6 R7.2 39.5,27.6 R8.2 39.568,27.468 39.568,26.068 v1(38.5,25)
pads on no net: J1.7 U3.2 U3.4 U3.5 U3.10 U3.11 U3.13 X1.3 X1.8 X1.9 X1.10

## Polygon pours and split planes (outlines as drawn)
GND on Top Layer "GND_L01_P000" (solid, pour order 0): 0,10 0,50 cw(c5,50) 5,55 48,55 cw(c48,50) 53,50 53,10 cw(c48,10) 48,5 5,5 cw(c5,10)
GND on Bottom Layer "GND_L02_P001" (solid, pour order 1): 0,10 0,50 cw(c5,50) 5,55 48,55 cw(c48,50) 53,50 53,10 cw(c48,10) 48,5 5,5 cw(c5,10)

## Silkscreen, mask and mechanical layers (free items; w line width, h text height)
Bottom Overlay:
  drawing of 46 lines, arcs and shapes, not listed
  text "BSPD" at 12.495,26.25 h5
  text "Guillem Ropero" at 12.75,23.775 h2.5
Mechanical 1:
  the board outline again, w0.5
